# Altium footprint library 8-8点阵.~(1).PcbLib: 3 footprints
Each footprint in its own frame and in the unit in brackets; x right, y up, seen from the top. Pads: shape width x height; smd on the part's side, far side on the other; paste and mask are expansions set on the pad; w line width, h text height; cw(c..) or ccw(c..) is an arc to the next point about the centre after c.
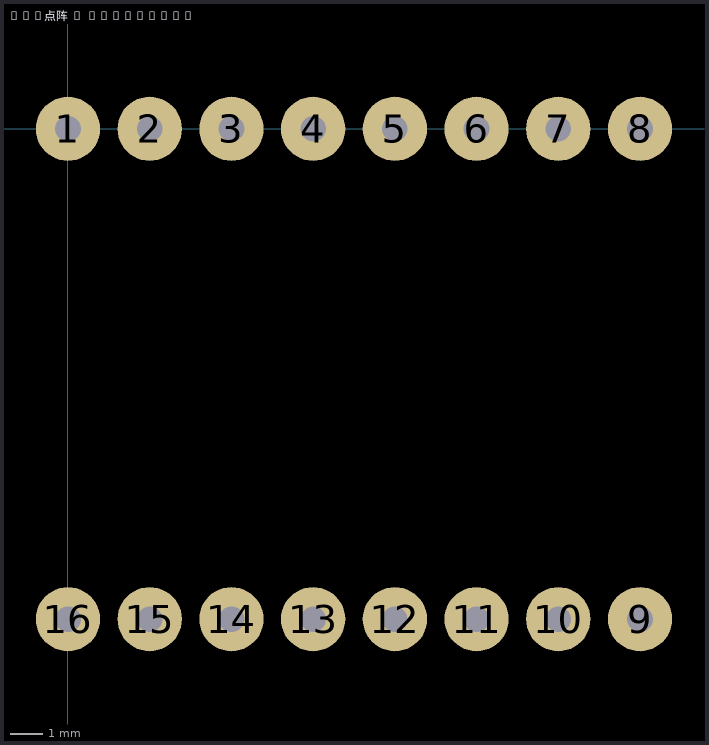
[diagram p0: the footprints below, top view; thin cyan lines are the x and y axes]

## 8-8点阵 [mm]

## 8-8点阵 - duplicate [mm]
pads (16):
  round 2 hole 0.8: 1(0,0) 2(2.54,0) 3(5.08,0) 4(7.62,0) 5(10.16,0) 6(12.7,0) 7(15.24,0) 8(17.78,0) 9(17.78,-15.24) 10(15.24,-15.24) 11(12.7,-15.24) 12(10.16,-15.24) 13(7.62,-15.24) 14(5.08,-15.24) 15(2.54,-15.24) 16(0,-15.24)

## PCBComponent_1 [mm]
